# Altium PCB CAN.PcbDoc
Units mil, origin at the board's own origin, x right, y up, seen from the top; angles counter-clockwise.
Board outline 1920 x 705 mil, 2 copper layers (Top Layer, Bottom Layer); 25 components, 23 nets, 96 pads, 21 vias.
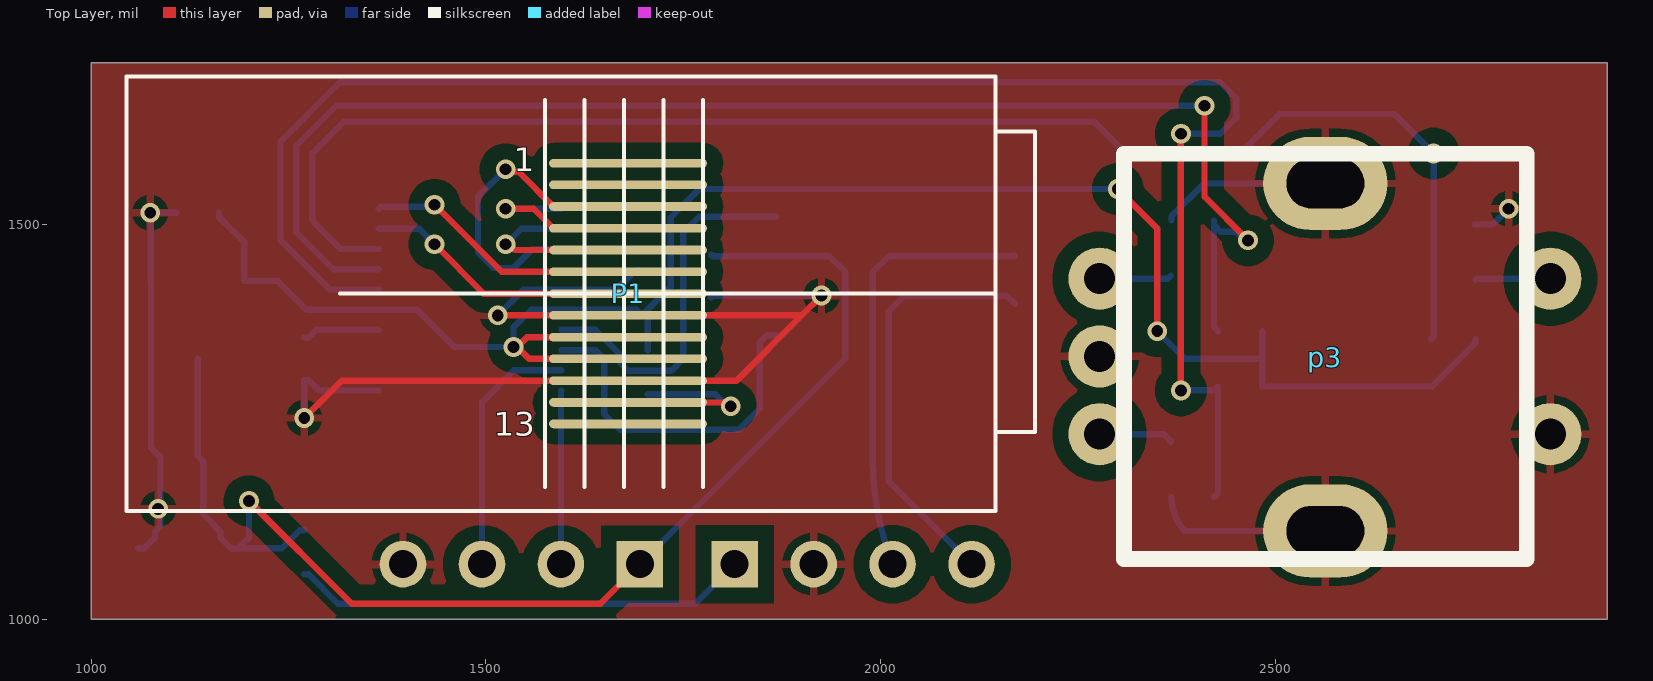
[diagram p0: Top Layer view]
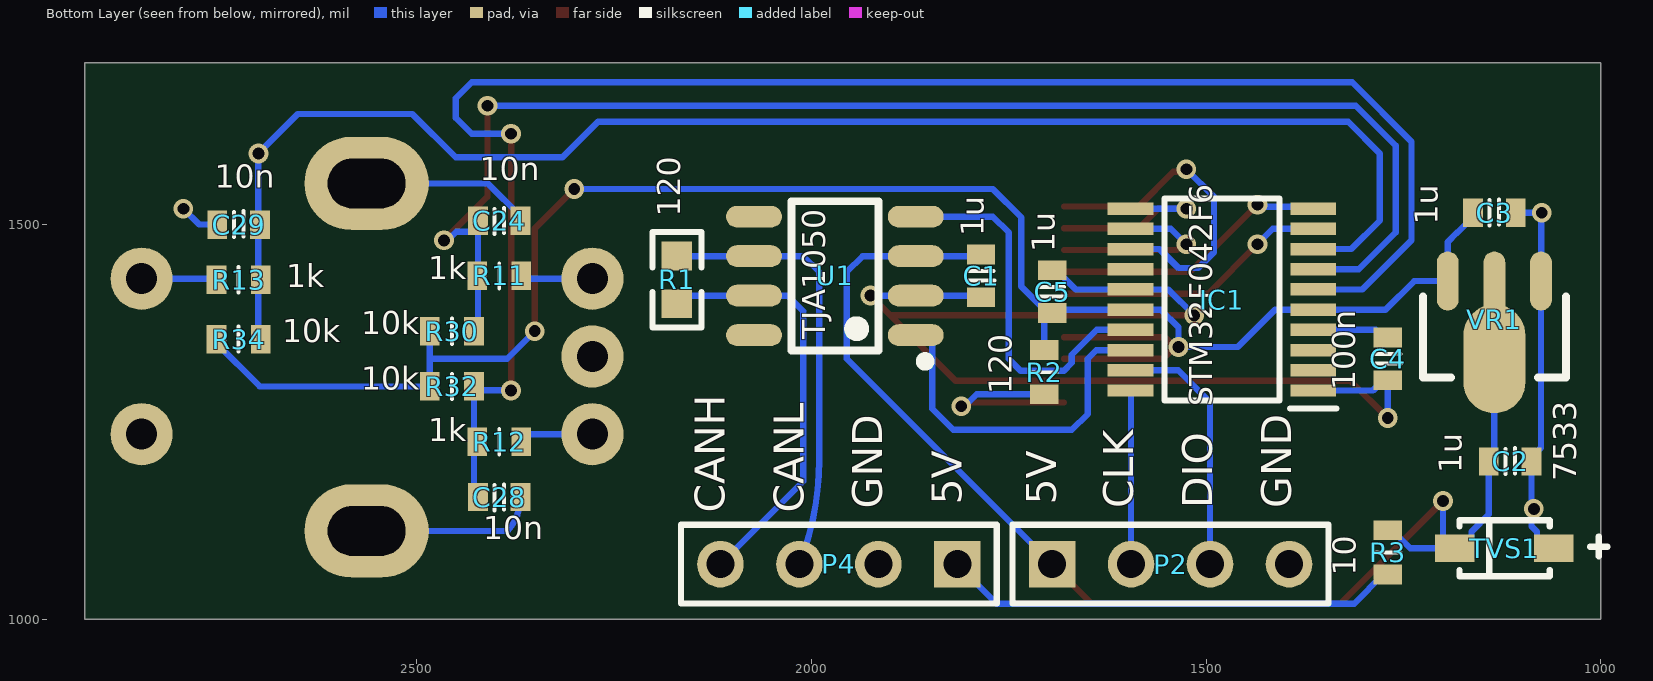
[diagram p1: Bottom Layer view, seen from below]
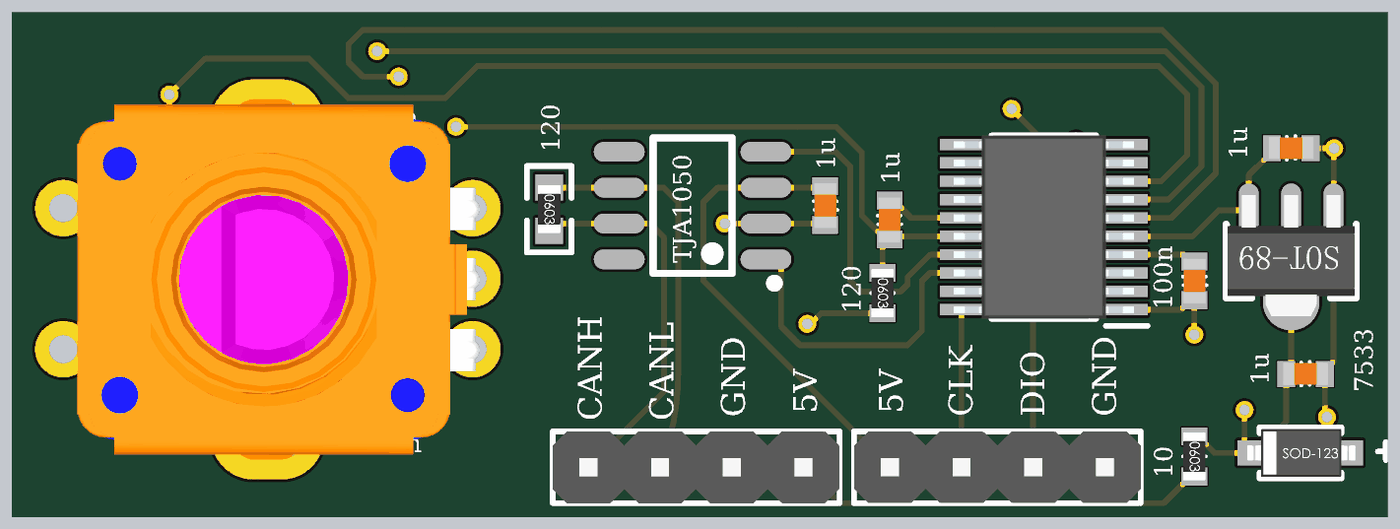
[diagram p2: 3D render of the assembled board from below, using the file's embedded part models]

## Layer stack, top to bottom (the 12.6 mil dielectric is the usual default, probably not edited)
Top Solder: solder mask 0.4, Solder Resist, Dk 3.5
Top Layer: signal copper 1.4
Dielectric 1: dielectric 12.6, FR-4, Dk 4.8
Bottom Layer: signal copper 1.4
Bottom Solder: solder mask 0.4, Solder Resist, Dk 3.5

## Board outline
1000,1000 2920,1000 2920,1705 1000,1705

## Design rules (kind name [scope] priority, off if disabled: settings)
Clearance [All] p1: gap=8 ignorepadtopadclearanceinfootprint=FALSE except(20: Arc-Fill Arc-Poly Arc-Region Track-Fill Track-Poly Track-Region SMDPad-Fill SMDPad-Poly SMDPad-Region THPad-Fill THPad-Poly THPad-Region Via-Fill Via-Poly Via-Region Fill-Fill Fill-Poly Fill-Region Poly-Poly Poly-Region Region-Region)
PolygonConnect [All] p1: connectstyle=Relief reliefconductorwidth=10 reliefentries=4 polygonreliefangle="90 Angle" airgapwidth=10
RoutingVias [All] p1: holewidth=28 width=50 viastyle="Through Hole" minholewidth=28 minwidth=50 maxholewidth=28 maxwidth=50
SolderMaskExpansion [All] p1: expansion=4 istentingtop=FALSE
Width [All] p1: maxlimit=100 minlimit=6 preferedwidth=10
30 further rules are at their usual default settings.

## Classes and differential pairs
component class CAn: C1 C2 C4 C5 C24 C28 C29 P1 P2 p3 P4 R1 R2 R3 R11 R12 R13 R30 R32 R34 TVS1 U1 VR1

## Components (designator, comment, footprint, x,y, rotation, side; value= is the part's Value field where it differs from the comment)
C1 "1uF" C_0603 1785,1435 r90 bottom
C2 "1uF" C_0603 1115,1200 r0 bottom
C3 "1uF" C_0603 1135,1515 r0 bottom
C4 "100nF" C_0603 1270,1330 r90 bottom
C5 "1uF" C_0603 1695,1415 r270 bottom
C24 "10nF" C_0603 2395,1505 r180 bottom
C28 "10nF" C_0603 2395,1155 r180 bottom
C29 "10nF" C_0603 2725,1500 r0 bottom
IC1 "STM32F042F6P6" CLT34BT6 1480,1405 r0 bottom
P1 "1.14/0.96_SPI_ST7789" 0.96_TFT_SPI_TOP 2145,1137.56 r0 top
P2 "P 4P" HDR1X4 1695,1070 r180 bottom
p3 "编码器 ec11" EC11 2380,1410 r270 top
P4 "P 4P" HDR1X4 1815,1070 r0 bottom
R1 "120" LC-0603_R 2170,1430 r270 bottom
R2 "120" R_0603 1705,1313 r270 bottom
R3 "10" R_0603 1270,1085 r270 bottom
R11 "1k" R_0603 2395,1435 r180 bottom
R12 "1k" R_0603 2395,1225 r180 bottom
R13 "1k" R_0603 2725,1430 r0 bottom
R30 "10k" R_0603 2455,1365 r180 bottom
R32 "10k" R_0603 2455,1295 r180 bottom
R34 "10k" R_0603 2725,1355 r180 bottom
TVS1 "5V" SOD123 1055,1090 r180 bottom
U1 "CAN/TJA1050T/CM" LC-SOIC-8_150mil 1970,1435 r90 bottom
VR1 "HT7533-1" LC-SOT-89(SOT-89-3) 1135,1428.43 r90 bottom

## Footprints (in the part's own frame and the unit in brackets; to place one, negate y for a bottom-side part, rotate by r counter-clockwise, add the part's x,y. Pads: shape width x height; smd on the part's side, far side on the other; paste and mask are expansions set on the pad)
0.96_TFT_SPI_TOP [mil]
  oval 200x11 smd: 1(-465,440) 2(-465,412.8) 3(-465,385.24) 4(-465,357.68) 5(-465,330.12) 6(-465,302.56) 7(-465,275) 8(-465,247.44) 9(-465,219.88) 10(-465,192.32) 11(-465,164.76) 12(-465,137.21) 13(-465,110)
  silkscreen extent -1100,0 50,550
C_0603 [mil]
  rect 25x36 smd mask+1.97: 1(-27,0) 2(27,0)
  silkscreen extent -6,-17 6,16, body extent -35,-20 35,20, height 55
CLT34BT6 [mm]
  rect 1.475x0.4 smd: 1(-2.938,2.925) 2(-2.938,2.275) 3(-2.938,1.625) 4(-2.938,0.975) 5(-2.938,0.325) 6(-2.938,-0.325) 7(-2.938,-0.975) 8(-2.938,-1.625) 9(-2.938,-2.275) 10(-2.938,-2.925) 11(2.938,-2.925) 12(2.938,-2.275) 13(2.938,-1.625) 14(2.938,-0.975) 15(2.938,-0.325) 16(2.938,0.325) 17(2.938,0.975) 18(2.938,1.625) 19(2.938,2.275) 20(2.938,2.925)
  silkscreen extent -3.67,-3.25 1.85,3.5, body extent -3.2,-3.25 3.2,3.25, height 1.2
EC11 [mm] "编码器"
  round 2 hole 1: A(-0.544,-2.616) B(4.456,-2.616) C(1.956,-2.616) D(-0.544,11.884) E(4.456,11.884)
  oval 3x4 hole 1.6 slot 2.5 at 90 deg: F(7.569,4.648) G(-3.607,4.648)
  silkscreen extent -4.56,-1.83 8.47,11.13, body extent -5.01,-2.87 8.98,11.38, height 20.05
HDR1X4 [mm] "Connector; Header; 4 Position"
  rect 1.5x1.5 hole 0.9: 1(0,0)
  round 1.5 hole 0.9: 2(2.54,0) 3(5.08,0) 4(7.62,0)
  silkscreen extent -1.27,-1.27 8.89,1.27, body extent -1.26,-1.27 8.9,1.27, height 8.54
LC-0603_R [mm]
  rect 0.93x0.98 smd: 1(-0.77,0) 2(0.77,0)
  silkscreen extent -1.53,-0.79 1.54,0.79, body extent -0.85,-0.4 0.85,0.4, height 0.56
LC-SOIC-8_150mil [mm]
  oval 0.7x1.8 smd: 1(-1.905,-2.6) 2(-0.635,-2.6) 3(0.635,-2.6) 4(1.905,-2.6) 5(1.905,2.6) 6(0.635,2.6) 7(-0.635,2.6) 8(-1.905,2.6)
  silkscreen extent -2.9,-3.05 2.4,1.4
LC-SOT-89(SOT-89-3) [mm]
  oval 1.9x0.7 smd: 1(0,-1.5) 3(0,1.5)
  oval 3.5x2 smd: 2(-2.5,0)
  oval 2.1x0.7 smd: 2(-0.1,0)
  silkscreen extent -3.1,-2.3 -0.5,2.3, body extent -3.75,-2.25 0.55,2.25, height 1.51
R_0603 [mil]
  rect 25x36 smd mask+1.97: 1(-28,0) 2(28,0)
  silkscreen extent 0,-16 0,16, body extent -36,-20 36,20, height 22
SOD123 [mil] "1206"
  rect 50x35 smd: A(-5,0) K(-130,0)
  silkscreen extent -124,-35 63,35, body extent -142,-34 10,33, height 56

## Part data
C1 C2 C3 C4 C5 C24 C28 C29: library part 贴片电容_
IC1: "Integrated Circuit", Manufacturer_Name=STMicroelectronics, Mouser Part Number=511-STM32F042F6P6
R1: library part "0603 10KΩ (1002) 1%", "贴片电阻", Package=0603, SuppliersPartNumber=C25804
R2 R3 R11 R12 R13 R30 R32 R34: library part 贴片电阻
TVS1: library part SOD, "二极管", Package=SOD-323, SuppliersPartNumber=C2128
U1: "CAN", Package=SOIC-8_150mil, SuppliersPartNumber=C6952
VR1: library part "SOT-89 HT7533-1", "低压差线性稳压(LDO)", Package=SOT-89, SuppliersPartNumber=C14289

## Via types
v1: diameter 25, hole 15, Top Layer to Bottom Layer, 21 vias

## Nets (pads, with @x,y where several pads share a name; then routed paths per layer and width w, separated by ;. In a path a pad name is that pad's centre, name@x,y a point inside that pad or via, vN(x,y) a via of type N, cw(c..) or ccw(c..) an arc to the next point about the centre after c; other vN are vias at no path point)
3V3: C3.2 C5.2 IC1.5 IC1.16 P1.9 P1.10 R2.1 R30.1 R32.1 R34.1 VR1.3 | length 2455
  Top Layer w8: v1(1535,1345) v1@1539.41,1345 ; P1.10 1554.53,1329.88 v1@1539.41,1345 ; P1.9 1552.04,1357.44 1539.6,1345 v1@1539.41,1345 ; v1(2300,1545) 2350,1495 v1(2350,1365)
  Bottom Layer w8: C3.2 1162,1509.5 1182.09,1489.41 1182.47,1489.41 1194.06,1477.83 VR1.3 1236.57,1428.43 1272.8,1392.2 IC1.5 1412.8,1392.2 1460,1345 v1(1535,1345) 1535,1370 1557.2,1392.2 1690.8,1392.2 C5.2 C5.2@1700.5,1388 ; R2.1 1705,1383.5 C5.2@1700.5,1388 ; v1(2300,1545) 1770,1545 1734,1509 1734,1421.5 C5.2@1700.5,1388 ; v1(2350,1365) 2385,1330 2483,1330 ; R30.1 2483,1330 ; R34.1 2753,1349.5 2698.5,1295 R32.1 2483,1330
5V: C1.2 C2.2 P2.1 R3.1 TVS1.K U1.3 VR1.2 | length 1651.6
  Top Layer w8: v1(1200,1150) 1330,1020 1645,1020 P2.1
  Bottom Layer w8: VR1.2@1135,1330 1135,1207 C2.2 1142,1133 1164,1111 1164,1103.5 1177.5,1090 TVS1.K TVS1.K@1186.5,1090 ; v1(1200,1150) 1200,1103.5 TVS1.K@1186.5,1090 ; R3.1 1264.5,1113 1241.5,1090 TVS1.K@1186.5,1090 ; P2.1 1955,1330 1955,1440 1935,1460 U1.3 1787,1460 C1.2
A: C24.1 IC1.7 R11.1 R30.2 | length 1791
  Top Layer w8: v1(2410,1650.5) 2410,1535 v1(2465,1480)
  Bottom Layer w8: IC1.7 1306.61,1443.39 1260,1490 1260,1600 1310.5,1650.5 v1(2410,1650.5) ; C24.1 C24.1@2422,1499.5 ; R30.2 2422,1370 C24.1@2422,1499.5 ; v1(2465,1480) 2460.4,1480 2449.4,1491 2430.5,1491 C24.1@2422,1499.5
B: C28.1 IC1.6 R12.1 R32.2 | length 2143.9
  Top Layer w8: v1(2380,1290) v1(2380,1615)
  Bottom Layer w8: IC1.6 1302.2,1417.8 1240,1480 1240,1605 1315,1680 2430,1680 2450,1660 2450,1635 2430,1615 v1(2380,1615) ; v1(2380,1290) 2422,1290 R32.2 2427,1160 C28.1
CAN_RX: IC1.17 U1.4 | length 473.7
  Bottom Layer w8: IC1.17 1638.39,1366.61 1670,1335 1670,1325 1680,1315 1735,1315 1750,1330 1750,1490 1770,1510 U1.4
CAN_TX: IC1.18 U1.1 | length 454
  Bottom Layer w8: IC1.18 1638.98,1341.02 1650,1330 1650,1260 1670,1240 1820,1240 1846.58,1266.58 1846.58,1350.96 1855.62,1360 U1.1
CANH: P4.4 R1.2 U1.7 | length 536.2
  Bottom Layer w8: P4.4 2010,1175 2010,1390.31 2029.69,1410 U1.7 2159.68,1410 R1.2
CANL: P4.3 R1.1 U1.6 | length 561.6
  Bottom Layer w8: P4.3 cw(c2349.33,1201.69) 1990,1201.99 1990,1440 2010,1460 U1.6 2169.69,1460 R1.1
CS: IC1.9 P1.7 | length 349.6
  Top Layer w8: v1(1435,1475) 1497.44,1412.56 P1.7
  Bottom Layer w8: IC1.9 1415.43,1494.57 v1(1435,1475)
D/C: IC1.12 P1.5 | length 236.8
  Top Layer w8: v1(1525,1475) 1529.6,1475 1536.92,1467.68 P1.5
  Bottom Layer w8: v1(1525,1475) 1544.57,1494.57 IC1.12
GND: C1.1 C2.1 C3.1 C4.1 C5.1 C24.2 C28.2 C29.2 IC1.1 IC1.15 P1.8 P1.11 P2.4 p3.C p3.E p3.F p3.G P4.2 TVS1.A U1.2 VR1.1 | length 2569.7
  Top Layer w8: v1(1270,1255) 1317.32,1302.32 P1.11 1817.32,1302.32 1900,1385 ; v1(1515,1385) P1.8 1900,1385 ; v1(1925,1410) 1900,1385
  Bottom Layer w8: TVS1.A 1067.5,1090 1081,1103.5 1081,1111 1088,1118 C2.1 1088,1205.5 1075.94,1217.56 VR1.1 1075.47,1428.9 1075.47,1514.53 v1(1075,1515) ; v1@1075.94,1514.06 1076.89,1515 C3.1 ; v1(1270,1255) C4.1 1275.5,1303 1288.66,1289.84 IC1.1 ; v1(1515,1385) 1547.8,1417.8 1665.3,1417.8 1689.5,1442 C5.1 ; C1.1 1787,1410 U1.2 v1(1925,1410) ; C28.2 ccw(c2431.77,1155) 2384.68,1112 p3.F ; C24.2 2368,1510.5 2409.5,1552 p3.G ; C29.2 2775,1500 v1(2795,1520)
  other v1: 1085,1140
K: C29.1 IC1.8 R13.1 R34.2 | length 1919.2
  Bottom Layer w8: IC1.8 1316.02,1468.98 1280,1505 1280,1590 1320,1630 2270,1630 2315,1585 2450,1585 2505,1640 2650,1640 v1(2700,1590) 2700,1500 2700,1430 2700,1358 R34.2
NetC4_2: C4.2 IC1.4 | length 98.3
  Bottom Layer w8: C4.2 1275.5,1357 1285.11,1366.61 IC1.4
NetP1_12: P1.12 R2.2 | length 243.2
  Top Layer w8: P1.12 1800.63,1274.77 1805.4,1270 v1(1810,1270)
  Bottom Layer w8: R2.2 1790.4,1285 1805.4,1270 v1(1810,1270)
Netp3_A: p3.A R11.2 | length 91.5
  Bottom Layer w8: p3.A 2363.43,1431.43 R11.2
Netp3_B: p3.B R12.2 | length 94.6
  Bottom Layer w8: p3.B 2358.5,1234.57 2367,1226.07 R12.2
Netp3_D: p3.D R13.2 | length 95.5
  Bottom Layer w8: R13.2 2754.43,1431.43 p3.D
NetP4_1: P4.1 R3.2 | length 581
  Bottom Layer w8: R3.2 1275.5,1057 1312.5,1020 1765,1020 P4.1
RST: IC1.10 P1.6 | length 352.8
  Top Layer w8: v1(1435,1525) 1519.88,1440.12 P1.6
  Bottom Layer w8: IC1.10 1366.75,1522.58 1432.58,1522.58 v1(1435,1525)
SPI1_MOSI: IC1.13 P1.3 | length 417.9
  Top Layer w8: v1(1525,1570) 1528.25,1566.75 1541.55,1566.75 1585.5,1522.8 P1.3
  Bottom Layer w8: v1(1525,1570) 1490,1535 1490,1465 1510,1445 1535,1445 1558.98,1468.98 IC1.13
SPI1_SCK: IC1.11 P1.4 | length 236
  Top Layer w8: v1(1525,1520) 1560.74,1520 1585.5,1495.24 P1.4
  Bottom Layer w8: v1(1525,1520) 1525.08,1520.08 1595.59,1520.08 IC1.11
SWCLK: IC1.20 P2.2 | length 220.1
  Bottom Layer w8: P2.2 1595,1289.17 IC1.20
SWDIO: IC1.19 P2.3 | length 322.4
  Bottom Layer w8: P2.3 1495,1275 1535.43,1315.43 IC1.19
pads on no net: IC1.2 IC1.3 IC1.14 P1.1 P1.2 P1.13 U1.5 U1.8

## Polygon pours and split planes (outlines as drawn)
GND on Top Layer "NONET_L-01_P-001" (solid, pour order 0): 1000,1705 1000,1000 2920,1000 2920,1705

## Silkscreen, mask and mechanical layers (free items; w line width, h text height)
Bottom Overlay:
  text "10n" at 2420,1546.25 h50
  text "10n" at 2755,1536.25 h50
  text "120" at 2155.69,1510 h50 r270
  text "1u" at 1196.41,1500 h50 r270
  text "1u" at 1771.41,1485 h50 r270
  text "1u" at 1681.41,1465 h50 r270
  text "1k" at 2485,1420.69 h50
  text "1k" at 2665,1410.69 h50
  text "TJA1050" at 1972.1,1355 h50 r270
  text "10k" at 2570,1350.69 h50
  text "10k" at 2670,1340.69 h50
  text "100n" at 1301.25,1290 h50 r270
  text "120" at 1735.69,1285 h50 r270
  text "10k" at 2570,1280.69 h50
  text "STM32F042F6" at 1481.85,1269.98 h50 r270
  text "1k" at 2485,1215.69 h50
  text "1u" at 1166.41,1185 h50 r270
  text "7533" at 1021.15,1175 h50 r270
  text "5V" at 1676.83,1145 h65 r270
  text "5V" at 1796.83,1145 h65 r270
  text "GND" at 1379.48,1140.83 h65 r270
  text "DIO" at 1479.48,1140.83 h65 r270
  text "CLK" at 1579.72,1140.83 h65 r270
  text "GND" at 1897.25,1140 h65 r270
  text "CANL" at 1997.1,1135 h65 r270
  text "CANH" at 2096.89,1135 h65 r270
  text "10n" at 2415,1091.25 h50
  text "10" at 1300.69,1055 h50 r270
Mechanical 1:
  lines w3: 995,995 2925,995 2925,1710 995,1710 995,995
